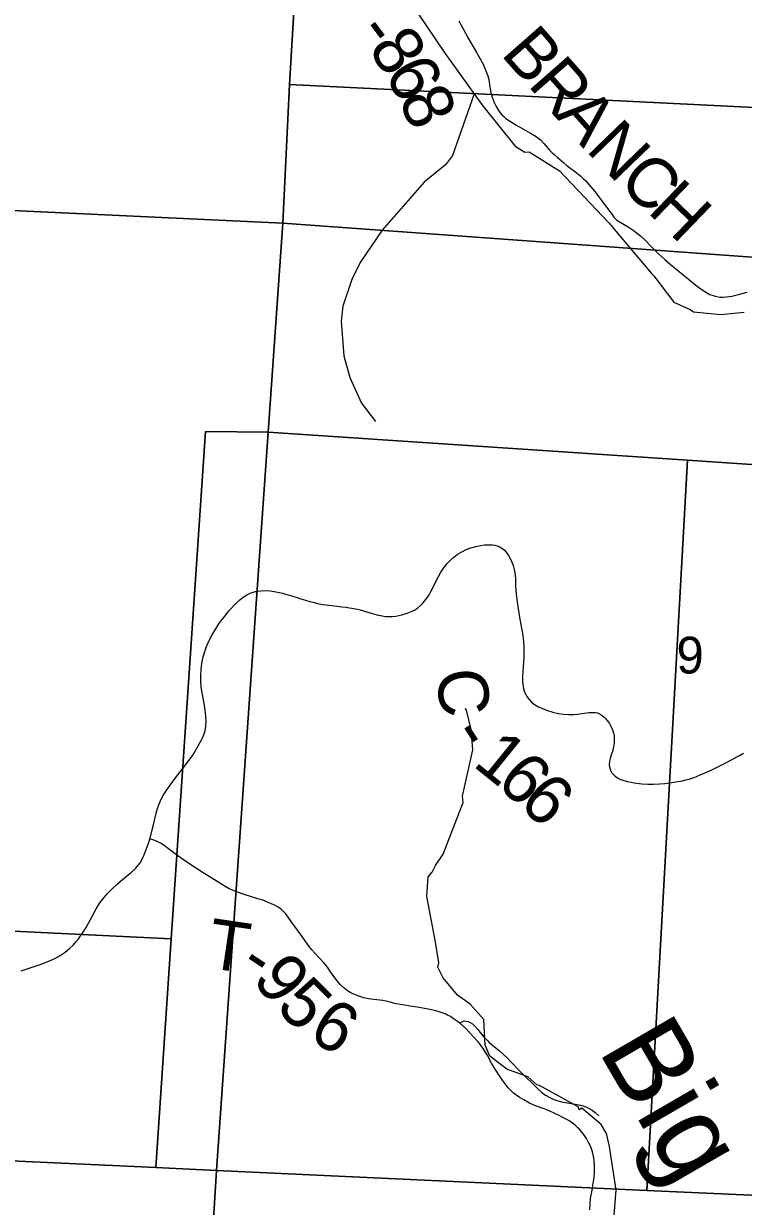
# Model space of a CAD drawing. Extents: x 0 to 34, y 0 to 22.
# Drawn here: x 4.739 to 5.558, y 15.208 to 16.555 of the extents above; entities that cross this region are included whole.
import ezdxf

# ---------------------------------------------------------------- set-up
doc = ezdxf.new("R2010")
doc.units = 0
for name, color, linetype in [('GM_X_County_Road', 7, 'Continuous'), ('GM_X_County_Road_Text', 7, 'Continuous'), ('GM_X_Minor_River', 7, 'Continuous'), ('GM_X_Minor_River_Text', 7, 'Continuous'), ('GM_X_Section', 7, 'Continuous'), ('GM_X_Section_Text', 7, 'Continuous'), ('GM_X_Township_Road', 7, 'Continuous'), ('GM_X_Township_Road_Text', 7, 'Continuous')]:
    doc.layers.add(name, color=color, linetype=linetype)

msp = doc.modelspace()

# ---------------------------------------------------------------- linework, layer by layer
at = {"layer": 'GM_X_County_Road'}
msp.add_lwpolyline([(4.7356, 15.4765), (4.7504, 15.4814), (4.7515, 15.4818), (4.7586, 15.4842), (4.7649, 15.4867), (4.7678, 15.4879), (4.7741, 15.4907), (4.78, 15.4941), (4.7857, 15.4979), (4.7906, 15.5018), (4.7947, 15.5057), (4.798, 15.5095), (4.8004, 15.5123), (4.8033, 15.5163), (4.8062, 15.5204), (4.8095, 15.5257), (4.8171, 15.54), (4.821, 15.547), (4.8253, 15.5538), (4.8297, 15.5597), (4.832, 15.5625), (4.8342, 15.5649), (4.8385, 15.5693), (4.8453, 15.5756), (4.8538, 15.5828), (4.861, 15.5887), (4.8661, 15.5933), (4.8694, 15.5971), (4.8712, 15.5997), (4.873, 15.603), (4.8746, 15.6065), (4.8756, 15.6087), (4.8784, 15.6157), (4.881, 15.6227), (4.8823, 15.6269), (4.8833, 15.6305), (4.8849, 15.6372), (4.8865, 15.6443), (4.8877, 15.6497), (4.8889, 15.6545), (4.8906, 15.6604), (4.8924, 15.6656), (4.8943, 15.6702), (4.8971, 15.6757), (4.9006, 15.6815), (4.9051, 15.6881), (4.9115, 15.6964), (4.9183, 15.7051), (4.9268, 15.7163), (4.9317, 15.7234), (4.9358, 15.7303), (4.9407, 15.7388), (4.9428, 15.7433), (4.9443, 15.7475), (4.9454, 15.7517), (4.946, 15.7561), (4.9463, 15.7611), (4.946, 15.7667), (4.9452, 15.7735), (4.9438, 15.7815), (4.9417, 15.793), (4.9407, 15.7997), (4.9402, 15.8064), (4.9401, 15.8131), (4.9405, 15.8199), (4.9414, 15.8266), (4.9426, 15.8326), (4.9444, 15.8391), (4.9468, 15.846), (4.9497, 15.8528), (4.953, 15.8592), (4.9571, 15.866), (4.9608, 15.8716), (4.964, 15.8762), (4.9663, 15.8791), (4.9685, 15.8821), (4.972, 15.8864), (4.9728, 15.8873), (4.98, 15.895), (4.9844, 15.8993), (4.9883, 15.9023), (4.9924, 15.9049), (4.9963, 15.9067), (4.9998, 15.9079), (5.004, 15.9089), (5.0088, 15.9095), (5.0144, 15.9096), (5.0191, 15.9093), (5.0236, 15.9088), (5.0296, 15.9075), (5.0332, 15.9066), (5.0356, 15.906), (5.0433, 15.9038), (5.0486, 15.902), (5.054, 15.9004), (5.0593, 15.8987), (5.0641, 15.8974), (5.0694, 15.8959), (5.0731, 15.8951), (5.0792, 15.8939), (5.0829, 15.8933), (5.089, 15.8925), (5.0952, 15.8918), (5.1007, 15.8912), (5.1056, 15.8906), (5.1093, 15.89), (5.1142, 15.8893), (5.1184, 15.8885), (5.1214, 15.8877), (5.1303, 15.8852), (5.1405, 15.8822), (5.1466, 15.8808), (5.1503, 15.8802), (5.1541, 15.88), (5.1578, 15.8801), (5.1622, 15.8807), (5.1689, 15.8822), (5.1749, 15.884), (5.1808, 15.8861), (5.1836, 15.8875), (5.1868, 15.8896), (5.1901, 15.8925), (5.1932, 15.8956), (5.1964, 15.8994), (5.1993, 15.9036), (5.2026, 15.9096), (5.2069, 15.9185), (5.2103, 15.9251), (5.2133, 15.9305), (5.2168, 15.9356), (5.2207, 15.9404), (5.2245, 15.9444), (5.2282, 15.9477), (5.2321, 15.9506), (5.2373, 15.9539), (5.2423, 15.9564), (5.2475, 15.9584), (5.2534, 15.96), (5.2588, 15.9611), (5.2631, 15.9616), (5.268, 15.9618), (5.2717, 15.9617), (5.2747, 15.9613), (5.2776, 15.9606), (5.2804, 15.9594), (5.283, 15.9579), (5.2853, 15.9559), (5.2878, 15.9533), (5.2903, 15.9498), (5.2925, 15.9461), (5.2942, 15.9422), (5.2956, 15.9381), (5.2971, 15.9322), (5.2979, 15.9274), (5.2983, 15.9231), (5.2985, 15.9152), (5.2988, 15.9103), (5.2992, 15.9059), (5.2995, 15.9023), (5.3006, 15.8937), (5.3009, 15.8918), (5.3031, 15.8791), (5.3063, 15.8607), (5.3074, 15.852), (5.3078, 15.8451), (5.308, 15.8373), (5.3079, 15.8337), (5.3076, 15.8278), (5.3067, 15.8176), (5.3064, 15.812), (5.3064, 15.807), (5.3068, 15.8026), (5.3076, 15.7983), (5.3088, 15.7941), (5.3101, 15.7912), (5.3113, 15.789), (5.314, 15.7855), (5.3166, 15.7827), (5.32, 15.7799), (5.3244, 15.7774), (5.3284, 15.7756), (5.3336, 15.7736), (5.3408, 15.7713), (5.3475, 15.7698), (5.353, 15.7689), (5.3587, 15.7684), (5.3618, 15.7684), (5.3643, 15.7685), (5.3688, 15.769), (5.3767, 15.77), (5.3822, 15.7707), (5.3846, 15.7709), (5.387, 15.7709), (5.3894, 15.7707), (5.3916, 15.7703), (5.3934, 15.7696), (5.3958, 15.7683), (5.3973, 15.7671), (5.3988, 15.7659), (5.4003, 15.7644), (5.4028, 15.7618), (5.4053, 15.7583), (5.4071, 15.7552), (5.4088, 15.7512), (5.4099, 15.7477), (5.4106, 15.7441), (5.4109, 15.7393), (5.4106, 15.7362), (5.4102, 15.7332), (5.4096, 15.7302), (5.4087, 15.7265), (5.4073, 15.7225), (5.406, 15.7183), (5.4055, 15.7152), (5.4051, 15.7114), (5.4054, 15.7088), (5.406, 15.7064), (5.4068, 15.7041), (5.4078, 15.7024), (5.4099, 15.7), (5.4118, 15.6983), (5.4144, 15.6965), (5.4172, 15.695), (5.4207, 15.6936), (5.4256, 15.6923), (5.4299, 15.6915), (5.4336, 15.6908), (5.4423, 15.6897), (5.4491, 15.6892), (5.4554, 15.6891), (5.4622, 15.6895), (5.4684, 15.69), (5.4758, 15.6909), (5.4832, 15.692), (5.4885, 15.6931), (5.4923, 15.6939), (5.4959, 15.6949), (5.5018, 15.6969), (5.5088, 15.6997), (5.5133, 15.7017), (5.5218, 15.7055), (5.5369, 15.7129), (5.5451, 15.7172), (5.551, 15.7205), (5.5542, 15.7221), (5.558, 15.7243)], dxfattribs=at)
at = {"layer": 'GM_X_Minor_River'}
for points in [[(5.1778, 16.5816), (5.2172, 16.5231), (5.2607, 16.4624), (5.2982, 16.4158), (5.3091, 16.4089), (5.3141, 16.4093), (5.3485, 16.3878), (5.4045, 16.3286), (5.4533, 16.2709), (5.4559, 16.2683), (5.4787, 16.2383), (5.4972, 16.23), (5.501, 16.227), (5.5323, 16.224), (5.5588, 16.2267)], [(5.2512, 16.4756), (5.2266, 16.4054), (5.2188, 16.3946), (5.1943, 16.3749), (5.1466, 16.3203), (5.1216, 16.2835), (5.112, 16.264), (5.102, 16.2336), (5.0999, 16.2166), (5.1029, 16.177), (5.1097, 16.1525), (5.1232, 16.1232), (5.1392, 16.1022)], [(5.4108, 15.198), (5.413, 15.2265), (5.4054, 15.2763), (5.402, 15.2911), (5.396, 15.3013), (5.374, 15.3199), (5.371, 15.318), (5.3699, 15.3214), (5.3256, 15.346), (5.3226, 15.3468), (5.3124, 15.3559), (5.2885, 15.3645), (5.2692, 15.3793), (5.2639, 15.3918), (5.2624, 15.4211), (5.2469, 15.4386), (5.2325, 15.4488), (5.2159, 15.4685), (5.2098, 15.4806), (5.2113, 15.4856), (5.2068, 15.5114), (5.1976, 15.5612), (5.1991, 15.5836), (5.2037, 15.5889), (5.2074, 15.5966), (5.2161, 15.6095), (5.2387, 15.6681), (5.238, 15.6753), (5.2497, 15.7281), (5.2481, 15.7513), (5.2428, 15.7734), (5.2413, 15.7753), (5.2417, 15.7756)]]:
    msp.add_lwpolyline(points, dxfattribs=at)
at = {"layer": 'GM_X_Section'}
for points in [[(4.0444, 17.3771), (5.0921, 17.3266), (5.0662, 16.9077), (5.041, 16.4863), (5.0334, 16.328), (4.4335, 16.3564), (3.9862, 16.3827), (3.9864, 16.3863), (3.9959, 16.5649), (4.0188, 16.9784)], [(6.1041, 16.8596), (6.0768, 16.4347), (5.041, 16.4863), (5.0662, 16.9077)], [(5.041, 16.4863), (6.0768, 16.4347), (6.0651, 16.2532), (5.0334, 16.328)], [(5.0334, 16.328), (5.0168, 16.0903), (4.9455, 16.091), (4.9066, 15.513), (4.383, 15.5384), (4.4335, 16.3564)], [(6.0651, 16.2532), (6.0647, 16.248), (6.0505, 16.0207), (5.4942, 16.0582), (5.0168, 16.0903), (5.0334, 16.328)], [(5.0168, 16.0903), (4.958, 15.2491), (4.889, 15.2523), (4.9066, 15.513), (4.9455, 16.091)], [(5.4942, 16.0582), (5.448, 15.2262), (4.958, 15.2491), (5.0168, 16.0903)], [(6.0505, 16.0207), (5.9993, 15.2017), (5.448, 15.2262), (5.4942, 16.0582)], [(3.9339, 15.5602), (4.383, 15.5384), (4.9066, 15.513), (4.889, 15.2523), (3.9173, 15.2973)], [(4.889, 15.2523), (4.958, 15.2491), (4.9464, 15.0576), (3.9051, 15.1052), (3.9173, 15.2973)]]:
    msp.add_lwpolyline(points, close=True, dxfattribs=at)
msp.add_lwpolyline([(4.9464, 15.0576), (4.958, 15.2491), (5.448, 15.2262), (5.9993, 15.2017)], dxfattribs=at)
at = {"layer": 'GM_X_Township_Road'}
for points in [[(5.2338, 16.5585), (5.2383, 16.5503), (5.2446, 16.539), (5.2499, 16.5299), (5.2537, 16.5235), (5.2581, 16.5155), (5.2615, 16.5092), (5.264, 16.5037), (5.2669, 16.4961), (5.268, 16.4918), (5.2691, 16.4835), (5.2704, 16.477), (5.2719, 16.4718), (5.2741, 16.4657), (5.2764, 16.461), (5.2785, 16.4573), (5.281, 16.4539), (5.2834, 16.4512), (5.285, 16.4497), (5.287, 16.4479), (5.2909, 16.4451), (5.2987, 16.4403), (5.304, 16.4371), (5.31, 16.4338), (5.3154, 16.4307), (5.3218, 16.4269), (5.324, 16.4255), (5.3268, 16.423), (5.3306, 16.4188), (5.3354, 16.4131), (5.3371, 16.4113), (5.3402, 16.4083), (5.3425, 16.4063), (5.3458, 16.4034), (5.3481, 16.4015), (5.3504, 16.3994), (5.3533, 16.3971), (5.357, 16.3938), (5.3585, 16.3927), (5.3614, 16.3903), (5.3654, 16.3875), (5.3689, 16.3849), (5.3728, 16.3817), (5.3756, 16.3791), (5.3783, 16.3763), (5.3819, 16.3721), (5.3886, 16.3641), (5.3908, 16.3611), (5.3998, 16.3493), (5.4058, 16.3415)], [(5.4058, 16.3415), (5.407, 16.34), (5.4084, 16.338), (5.4095, 16.3363), (5.4107, 16.3348), (5.4123, 16.3333), (5.4138, 16.3317), (5.4158, 16.3303), (5.4266, 16.324), (5.4323, 16.3203), (5.4373, 16.3166), (5.4406, 16.3139), (5.4459, 16.3087), (5.452, 16.3025), (5.4617, 16.2929), (5.4685, 16.2867), (5.4745, 16.2816), (5.495, 16.2646), (5.5036, 16.2575), (5.5107, 16.2524), (5.5159, 16.2491), (5.5198, 16.2471), (5.5245, 16.2454), (5.5274, 16.2446), (5.5311, 16.244), (5.5348, 16.2439), (5.5386, 16.2442), (5.5447, 16.2452), (5.5537, 16.2473), (5.5621, 16.2495)], [(5.3829, 15.2044), (5.3832, 15.2105), (5.3839, 15.2172), (5.3859, 15.2287), (5.3865, 15.2323), (5.3872, 15.2368), (5.3878, 15.241), (5.3882, 15.2466), (5.3882, 15.2547), (5.3879, 15.2603), (5.3871, 15.2653), (5.386, 15.2702), (5.384, 15.2761), (5.3816, 15.2811), (5.3793, 15.2854), (5.3769, 15.289), (5.3739, 15.2928), (5.3712, 15.296), (5.3694, 15.2976), (5.367, 15.2998), (5.3649, 15.3017), (5.3632, 15.303), (5.3602, 15.3051), (5.357, 15.3071), (5.3508, 15.3102), (5.348, 15.3116), (5.3425, 15.3145), (5.3374, 15.3167), (5.3298, 15.3196), (5.3211, 15.3229), (5.3143, 15.3259), (5.3077, 15.3294), (5.3025, 15.3326), (5.2963, 15.3373), (5.2936, 15.3398), (5.2902, 15.3434), (5.2856, 15.3492), (5.2803, 15.3568), (5.2752, 15.3645), (5.2711, 15.3715), (5.2661, 15.3808), (5.2632, 15.3856), (5.2596, 15.3907), (5.2558, 15.3956), (5.25, 15.4022), (5.2413, 15.4111), (5.2351, 15.4168), (5.231, 15.42), (5.2276, 15.4223), (5.2244, 15.4243), (5.2211, 15.4261), (5.2189, 15.4272), (5.2162, 15.4283), (5.2125, 15.4295), (5.2077, 15.4308), (5.1988, 15.4328), (5.1863, 15.435), (5.1783, 15.4361), (5.1699, 15.4376), (5.1608, 15.4394), (5.1583, 15.44), (5.1544, 15.4412), (5.1513, 15.4419), (5.1475, 15.4426), (5.1439, 15.4431), (5.1371, 15.4437), (5.131, 15.4445), (5.1256, 15.4457), (5.121, 15.4472), (5.1152, 15.4494), (5.1109, 15.4516), (5.1073, 15.4539), (5.1034, 15.4569), (5.0989, 15.4611), (5.0952, 15.4652), (5.0915, 15.47), (5.0872, 15.4766), (5.0844, 15.4806), (5.0826, 15.483), (5.0803, 15.4858), (5.0758, 15.4906), (5.0699, 15.4967), (5.0667, 15.5004), (5.0653, 15.5019), (5.0636, 15.5042), (5.0598, 15.5097), (5.0557, 15.5155), (5.0501, 15.5229), (5.0432, 15.5326), (5.0369, 15.5415), (5.0344, 15.5442), (5.0317, 15.5466), (5.0281, 15.5489), (5.0232, 15.5515), (5.016, 15.5549), (5.0108, 15.5569), (5.0049, 15.5587), (4.999, 15.5604), (4.9884, 15.5638), (4.9832, 15.5656), (4.978, 15.5675), (4.9725, 15.5699), (4.9678, 15.5725), (4.9618, 15.5762), (4.9558, 15.5801), (4.9496, 15.584), (4.9428, 15.5882), (4.9329, 15.5946), (4.9231, 15.6012), (4.914, 15.6076), (4.9035, 15.6153), (4.8985, 15.6191), (4.8944, 15.6218), (4.8905, 15.6238), (4.8877, 15.625), (4.8823, 15.6269)], [(5.2351, 15.4168), (5.2366, 15.4181), (5.2383, 15.4189), (5.2401, 15.4194), (5.2422, 15.4193), (5.2446, 15.4187), (5.2469, 15.4178), (5.2495, 15.4161), (5.2522, 15.4136), (5.2555, 15.4098), (5.2625, 15.4011), (5.2668, 15.3966), (5.2685, 15.395), (5.2704, 15.3933), (5.28, 15.3854), (5.2891, 15.3771), (5.2939, 15.3722), (5.2969, 15.369), (5.3002, 15.3653), (5.3102, 15.3552), (5.3174, 15.3484), (5.3236, 15.3423), (5.3285, 15.3379), (5.3326, 15.3349), (5.3375, 15.3321), (5.342, 15.33), (5.3455, 15.3288), (5.3509, 15.3274), (5.3662, 15.3247), (5.3729, 15.3234), (5.3765, 15.3224), (5.3794, 15.3213), (5.3824, 15.3196), (5.3856, 15.3178), (5.3891, 15.315), (5.3931, 15.3112)]]:
    msp.add_lwpolyline(points, dxfattribs=at)

# ---------------------------------------------------------------- texts
at = {"layer": 'GM_X_County_Road_Text'}
for s, rotation, p in [('C', 276.8307, (5.2077, 15.8177)), ('-', 302.6784, (5.2226, 15.7453)), ('1', 321.0253, (5.2484, 15.7109)), ('6', 317.3096, (5.2749, 15.6895)), ('6', 317.0906, (5.3005, 15.6658))]:
    msp.add_text(s, height=0.0568, rotation=rotation, dxfattribs=at).set_placement(p)
at = {"layer": 'GM_X_Minor_River_Text'}
msp.add_text('Big', height=0.09469, rotation=300.1353, dxfattribs=at).set_placement((5.3917, 15.3863))
at = {"layer": 'GM_X_Section_Text'}
msp.add_text('9', height=0.0419, rotation=0, dxfattribs=at).set_placement((5.4816, 15.8152))
at = {"layer": 'GM_X_Township_Road_Text'}
for s, rotation, p in [('-', 306.8199, (5.1163, 16.5451)), ('8', 303.4072, (5.1298, 16.5272)), ('B', 311.3477, (5.2805, 16.5207)), ('R', 311.3464, (5.3113, 16.4857)), ('6', 298.8464, (5.1484, 16.499)), ('8', 293.6243, (5.1647, 16.4696)), ('A', 311.6869, (5.3424, 16.4504)), ('N', 314.0513, (5.3774, 16.4112)), ('C', 315.9732, (5.4136, 16.3738)), ('H', 316.1221, (5.4473, 16.3412)), ('T', 351.5826, (4.9456, 15.4804)), ('-', 326.5903, (4.9816, 15.4765)), ('9', 308.4209, (4.9976, 15.4669)), ('5', 315.1774, (5.0242, 15.434)), ('6', 328.862, (5.0606, 15.4002))]:
    msp.add_text(s, height=0.0568, rotation=rotation, dxfattribs=at).set_placement(p)

doc.saveas('drawing.dxf')
